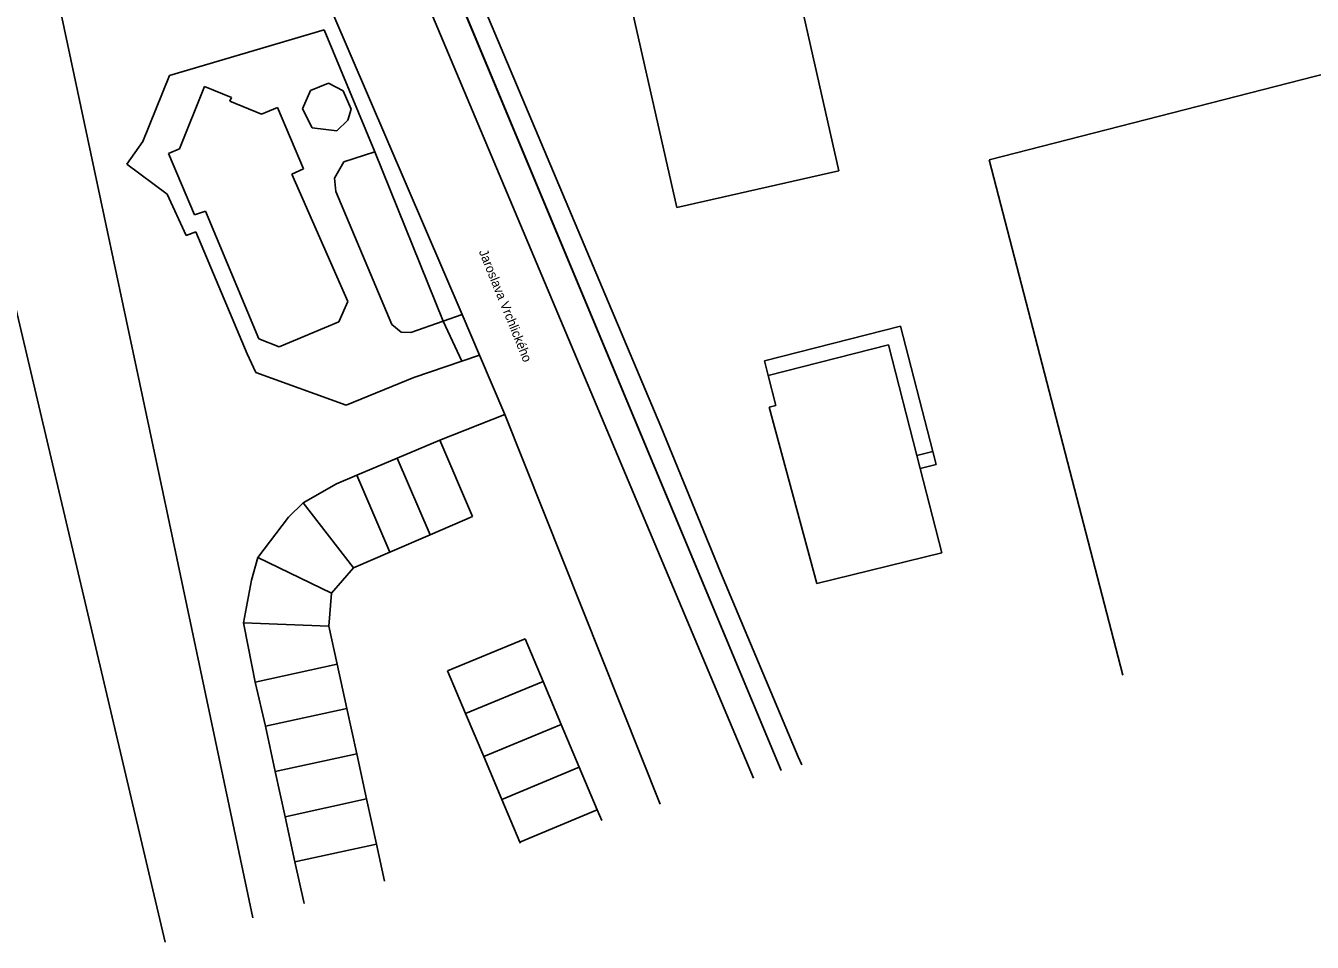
# Model space of a CAD drawing. Extents: x -452714 to -451134, y -1100194 to -1099694.
# Drawn here: x -451711.3 to -451613.9, y -1100007.9 to -1099938.4 of the extents above; entities that cross this region are included whole.
import ezdxf

# ---------------------------------------------------------------- set-up
doc = ezdxf.new("R2010")
doc.units = 0
doc.layers.add('Polohopis', color=7, linetype='Continuous')

msp = doc.modelspace()

# ---------------------------------------------------------------- linework, layer by layer
at = {"layer": 'Polohopis'}
for p, q in [((-451704.54, -1099873.82), (-451654.083, -1099994.837)), ((-451704.54, -1099873.82), (-451654.083, -1099994.837)), ((-451704.539, -1099873.82), (-451654.082, -1099994.836)), ((-451705.74, -1099877.629), (-451656.174, -1099995.42)), ((-451705.74, -1099877.63), (-451656.174, -1099995.42)), ((-451705.74, -1099877.63), (-451656.174, -1099995.42)), ((-451717.36, -1099896.27), (-451700.86, -1099973.87)), ((-451717.36, -1099896.27), (-451700.86, -1099973.87)), ((-451663.18, -1099968.8), (-451692.37, -1099899.639)), ((-451663.18, -1099968.8), (-451692.37, -1099899.64)), ((-451663.18, -1099968.8), (-451692.37, -1099899.64)), ((-451649.71, -1099949.42), (-451658.82, -1099909.22)), ((-451649.71, -1099949.42), (-451658.82, -1099909.22)), ((-451649.71, -1099949.42), (-451658.82, -1099909.22)), ((-451670.83, -1099913.11), (-451661.98, -1099952.2)), ((-451670.83, -1099913.11), (-451661.98, -1099952.2)), ((-451670.83, -1099913.11), (-451661.98, -1099952.2)), ((-451688.08, -1099937.34), (-451678.23, -1099960.31)), ((-451688.08, -1099937.34), (-451678.23, -1099960.31)), ((-451688.08, -1099937.34), (-451678.23, -1099960.31)), ((-451700.38, -1099942.2), (-451688.66, -1099938.74)), ((-451700.38, -1099942.2), (-451688.66, -1099938.74)), ((-451700.38, -1099942.2), (-451688.659, -1099938.74)), ((-451688.66, -1099938.74), (-451684.84, -1099947.99)), ((-451688.66, -1099938.74), (-451684.84, -1099947.99)), ((-451688.659, -1099938.74), (-451684.84, -1099947.99)), ((-451605.09, -1099940.08), (-451638.32, -1099948.6)), ((-451605.09, -1099940.08), (-451638.32, -1099948.6)), ((-451605.09, -1099940.08), (-451638.32, -1099948.6)), ((-451702.39, -1099947.2), (-451700.38, -1099942.2)), ((-451702.39, -1099947.2), (-451700.38, -1099942.2)), ((-451699.62, -1099947.76), (-451697.74, -1099943.04)), ((-451699.62, -1099947.76), (-451697.74, -1099943.04)), ((-451697.74, -1099943.04), (-451695.69, -1099943.88)), ((-451697.74, -1099943.04), (-451695.69, -1099943.88)), ((-451690.31, -1099944.73), (-451689.7, -1099943.35)), ((-451690.31, -1099944.73), (-451689.7, -1099943.35)), ((-451689.7, -1099943.35), (-451688.34, -1099942.8)), ((-451689.7, -1099943.35), (-451688.34, -1099942.8)), ((-451688.34, -1099942.8), (-451687.24, -1099943.36)), ((-451688.34, -1099942.8), (-451687.24, -1099943.36)), ((-451688.34, -1099942.8), (-451687.24, -1099943.36)), ((-451687.24, -1099943.36), (-451686.62, -1099944.75)), ((-451687.24, -1099943.36), (-451686.62, -1099944.75)), ((-451687.24, -1099943.36), (-451686.62, -1099944.75)), ((-451700.699, -1100007.851), (-451715.65, -1099944.45)), ((-451700.699, -1100007.851), (-451715.65, -1099944.45)), ((-451695.69, -1099943.88), (-451695.81, -1099944.16)), ((-451695.69, -1099943.88), (-451695.81, -1099944.16)), ((-451695.81, -1099944.16), (-451693.41, -1099945.15)), ((-451695.81, -1099944.16), (-451693.41, -1099945.15)), ((-451693.41, -1099945.15), (-451692.21, -1099944.64)), ((-451693.41, -1099945.15), (-451692.21, -1099944.64)), ((-451692.21, -1099944.64), (-451690.24, -1099949.28)), ((-451692.21, -1099944.64), (-451690.24, -1099949.28)), ((-451689.58, -1099946.18), (-451690.31, -1099944.73)), ((-451689.58, -1099946.18), (-451690.31, -1099944.73)), ((-451686.89, -1099945.58), (-451687.7, -1099946.39)), ((-451686.89, -1099945.58), (-451687.7, -1099946.39)), ((-451686.89, -1099945.58), (-451687.7, -1099946.389)), ((-451686.62, -1099944.75), (-451686.89, -1099945.58)), ((-451686.62, -1099944.75), (-451686.89, -1099945.58)), ((-451686.62, -1099944.75), (-451686.89, -1099945.58)), ((-451687.7, -1099946.39), (-451689.58, -1099946.18)), ((-451687.7, -1099946.39), (-451689.58, -1099946.18)), ((-451703.6, -1099948.92), (-451702.39, -1099947.2)), ((-451703.6, -1099948.92), (-451702.39, -1099947.2)), ((-451700.45, -1099948.11), (-451699.62, -1099947.76)), ((-451700.45, -1099948.11), (-451699.62, -1099947.76)), ((-451698.48, -1099952.77), (-451700.45, -1099948.11)), ((-451698.48, -1099952.77), (-451700.45, -1099948.11)), ((-451684.84, -1099947.99), (-451687.19, -1099948.74)), ((-451684.84, -1099947.99), (-451687.19, -1099948.74)), ((-451684.84, -1099947.99), (-451687.19, -1099948.74)), ((-451684.84, -1099947.99), (-451679.65, -1099960.81)), ((-451684.84, -1099947.99), (-451679.65, -1099960.81)), ((-451684.84, -1099947.99), (-451679.65, -1099960.81)), ((-451700.55, -1099951.19), (-451703.6, -1099948.92)), ((-451700.55, -1099951.19), (-451703.6, -1099948.92)), ((-451690.24, -1099949.28), (-451691.13, -1099949.67)), ((-451690.24, -1099949.28), (-451691.13, -1099949.67)), ((-451687.19, -1099948.74), (-451687.89, -1099949.98)), ((-451687.19, -1099948.74), (-451687.89, -1099949.98)), ((-451661.98, -1099952.2), (-451649.71, -1099949.42)), ((-451661.98, -1099952.2), (-451649.71, -1099949.42)), ((-451661.98, -1099952.2), (-451649.71, -1099949.42)), ((-451638.32, -1099948.6), (-451628.199, -1099987.61)), ((-451638.32, -1099948.6), (-451628.199, -1099987.61)), ((-451638.32, -1099948.6), (-451628.199, -1099987.61)), ((-451691.13, -1099949.67), (-451686.89, -1099959.32)), ((-451691.13, -1099949.67), (-451686.89, -1099959.32)), ((-451687.89, -1099949.98), (-451687.8, -1099950.99)), ((-451687.89, -1099949.98), (-451687.8, -1099950.99)), ((-451699.11, -1099954.33), (-451700.55, -1099951.19)), ((-451699.11, -1099954.33), (-451700.55, -1099951.19)), ((-451687.8, -1099950.99), (-451683.55, -1099961.06)), ((-451687.8, -1099950.99), (-451683.55, -1099961.06)), ((-451687.8, -1099950.99), (-451683.55, -1099961.06)), ((-451697.66, -1099952.48), (-451698.48, -1099952.77)), ((-451697.66, -1099952.48), (-451698.48, -1099952.77)), ((-451693.62, -1099962.16), (-451697.66, -1099952.48)), ((-451693.62, -1099962.16), (-451697.66, -1099952.48)), ((-451698.39, -1099954.05), (-451699.11, -1099954.33)), ((-451698.39, -1099954.05), (-451699.11, -1099954.33)), ((-451694.5, -1099963.29), (-451698.39, -1099954.05)), ((-451694.5, -1099963.29), (-451698.39, -1099954.05)), ((-451686.89, -1099959.32), (-451687.57, -1099960.86)), ((-451686.89, -1099959.32), (-451687.57, -1099960.86)), ((-451687.57, -1099960.86), (-451692.07, -1099962.77)), ((-451687.57, -1099960.86), (-451692.07, -1099962.77)), ((-451683.55, -1099961.06), (-451682.84, -1099961.65)), ((-451683.55, -1099961.06), (-451682.84, -1099961.65)), ((-451683.55, -1099961.06), (-451682.84, -1099961.65)), ((-451682.12, -1099961.67), (-451679.65, -1099960.81)), ((-451682.12, -1099961.67), (-451679.65, -1099960.81)), ((-451682.12, -1099961.67), (-451679.65, -1099960.81)), ((-451679.65, -1099960.81), (-451678.23, -1099960.31)), ((-451679.65, -1099960.81), (-451678.23, -1099960.31)), ((-451679.65, -1099960.81), (-451678.23, -1099960.31)), ((-451679.65, -1099960.81), (-451678.26, -1099963.85)), ((-451679.65, -1099960.81), (-451678.26, -1099963.85)), ((-451679.65, -1099960.81), (-451678.26, -1099963.85)), ((-451678.23, -1099960.31), (-451676.91, -1099963.39)), ((-451678.23, -1099960.31), (-451676.91, -1099963.39)), ((-451678.23, -1099960.31), (-451676.909, -1099963.389)), ((-451655.33, -1099963.83), (-451645.03, -1099961.2)), ((-451655.33, -1099963.83), (-451645.03, -1099961.2)), ((-451655.33, -1099963.83), (-451645.03, -1099961.2)), ((-451645.03, -1099961.2), (-451642.6, -1099970.68)), ((-451645.03, -1099961.2), (-451642.6, -1099970.68)), ((-451645.03, -1099961.2), (-451642.599, -1099970.68)), ((-451692.07, -1099962.77), (-451693.62, -1099962.16)), ((-451692.07, -1099962.77), (-451693.62, -1099962.16)), ((-451682.84, -1099961.65), (-451682.12, -1099961.67)), ((-451682.84, -1099961.65), (-451682.12, -1099961.67)), ((-451682.84, -1099961.65), (-451682.12, -1099961.67)), ((-451655.05, -1099964.94), (-451645.94, -1099962.6)), ((-451655.05, -1099964.94), (-451645.94, -1099962.6)), ((-451655.05, -1099964.94), (-451645.94, -1099962.6)), ((-451645.94, -1099962.6), (-451643.8, -1099970.99)), ((-451645.94, -1099962.6), (-451643.8, -1099970.99)), ((-451645.94, -1099962.6), (-451643.8, -1099970.99)), ((-451693.84, -1099964.71), (-451694.5, -1099963.29)), ((-451693.84, -1099964.71), (-451694.5, -1099963.29)), ((-451678.26, -1099963.85), (-451681.89, -1099965.09)), ((-451678.26, -1099963.85), (-451681.89, -1099965.09)), ((-451678.26, -1099963.85), (-451681.89, -1099965.09)), ((-451678.26, -1099963.85), (-451676.909, -1099963.389)), ((-451678.26, -1099963.85), (-451676.91, -1099963.39)), ((-451678.26, -1099963.85), (-451676.91, -1099963.39)), ((-451676.91, -1099963.39), (-451674.99, -1099967.87)), ((-451676.91, -1099963.39), (-451674.99, -1099967.87)), ((-451676.909, -1099963.389), (-451674.99, -1099967.87)), ((-451655.05, -1099964.94), (-451655.33, -1099963.83)), ((-451655.05, -1099964.94), (-451655.33, -1099963.83)), ((-451655.05, -1099964.94), (-451655.33, -1099963.83)), ((-451687.01, -1099967.17), (-451693.84, -1099964.71)), ((-451687.01, -1099967.17), (-451693.84, -1099964.71)), ((-451681.89, -1099965.09), (-451687.01, -1099967.17)), ((-451681.89, -1099965.09), (-451687.01, -1099967.17)), ((-451681.89, -1099965.09), (-451687.01, -1099967.17)), ((-451654.47, -1099967.19), (-451655.05, -1099964.94)), ((-451654.47, -1099967.19), (-451655.05, -1099964.94)), ((-451654.469, -1099967.19), (-451655.05, -1099964.94)), ((-451679.92, -1099969.82), (-451674.99, -1099967.87)), ((-451679.92, -1099969.82), (-451674.99, -1099967.87)), ((-451679.92, -1099969.82), (-451674.99, -1099967.87)), ((-451674.99, -1099967.87), (-451663.245, -1099997.394)), ((-451674.99, -1099967.87), (-451663.245, -1099997.394)), ((-451674.99, -1099967.87), (-451663.245, -1099997.394)), ((-451654.98, -1099967.32), (-451654.47, -1099967.19)), ((-451654.98, -1099967.32), (-451654.47, -1099967.19)), ((-451654.98, -1099967.32), (-451654.469, -1099967.19)), ((-451651.37, -1099980.67), (-451654.98, -1099967.32)), ((-451651.37, -1099980.67), (-451654.98, -1099967.32)), ((-451651.37, -1099980.67), (-451654.98, -1099967.32)), ((-451658.67, -1099979.83), (-451663.18, -1099968.8)), ((-451658.67, -1099979.83), (-451663.18, -1099968.8)), ((-451658.67, -1099979.83), (-451663.18, -1099968.8)), ((-451679.92, -1099969.82), (-451683.14, -1099971.18)), ((-451679.92, -1099969.82), (-451683.14, -1099971.18)), ((-451679.92, -1099969.82), (-451683.14, -1099971.18)), ((-451677.43, -1099975.61), (-451679.92, -1099969.82)), ((-451677.43, -1099975.61), (-451679.92, -1099969.82)), ((-451677.43, -1099975.61), (-451679.92, -1099969.82)), ((-451643.8, -1099970.99), (-451642.6, -1099970.68)), ((-451643.8, -1099970.99), (-451642.6, -1099970.68)), ((-451643.8, -1099970.99), (-451642.599, -1099970.68)), ((-451642.6, -1099970.68), (-451642.35, -1099971.66)), ((-451642.6, -1099970.68), (-451642.35, -1099971.66)), ((-451642.599, -1099970.68), (-451642.349, -1099971.66)), ((-451683.14, -1099971.18), (-451686.2, -1099972.48)), ((-451683.14, -1099971.18), (-451686.2, -1099972.48)), ((-451683.14, -1099971.18), (-451680.65, -1099976.99)), ((-451683.14, -1099971.18), (-451680.65, -1099976.99)), ((-451683.14, -1099971.18), (-451680.65, -1099976.99)), ((-451643.8, -1099970.99), (-451643.55, -1099971.96)), ((-451643.8, -1099970.99), (-451643.55, -1099971.96)), ((-451643.8, -1099970.99), (-451643.55, -1099971.96)), ((-451642.35, -1099971.66), (-451643.55, -1099971.96)), ((-451642.35, -1099971.66), (-451643.55, -1099971.96)), ((-451642.349, -1099971.66), (-451643.55, -1099971.96)), ((-451686.2, -1099972.48), (-451687.74, -1099973.13)), ((-451686.2, -1099972.48), (-451687.74, -1099973.13)), ((-451686.2, -1099972.48), (-451683.7, -1099978.3)), ((-451686.2, -1099972.48), (-451683.7, -1099978.3)), ((-451643.55, -1099971.96), (-451641.91, -1099978.37)), ((-451643.55, -1099971.96), (-451641.91, -1099978.37)), ((-451643.55, -1099971.96), (-451641.909, -1099978.37)), ((-451700.86, -1099973.87), (-451694.076, -1100006.002)), ((-451700.86, -1099973.87), (-451694.076, -1100006.002)), ((-451687.74, -1099973.13), (-451690.27, -1099974.58)), ((-451687.74, -1099973.13), (-451690.27, -1099974.58)), ((-451690.27, -1099974.58), (-451691.36, -1099975.65)), ((-451690.27, -1099974.58), (-451691.36, -1099975.65)), ((-451690.27, -1099974.58), (-451686.44, -1099979.5)), ((-451690.27, -1099974.58), (-451686.44, -1099979.5)), ((-451691.36, -1099975.65), (-451693.69, -1099978.7)), ((-451691.36, -1099975.65), (-451693.69, -1099978.7)), ((-451680.65, -1099976.99), (-451677.43, -1099975.61)), ((-451680.65, -1099976.99), (-451677.43, -1099975.61)), ((-451680.65, -1099976.99), (-451677.43, -1099975.61)), ((-451683.7, -1099978.3), (-451680.65, -1099976.99)), ((-451683.7, -1099978.3), (-451680.65, -1099976.99)), ((-451683.7, -1099978.3), (-451680.65, -1099976.99)), ((-451693.69, -1099978.7), (-451694.17, -1099980.44)), ((-451693.69, -1099978.7), (-451694.17, -1099980.44)), ((-451693.69, -1099978.7), (-451688.12, -1099981.4)), ((-451693.69, -1099978.7), (-451688.12, -1099981.4)), ((-451686.44, -1099979.5), (-451683.7, -1099978.3)), ((-451686.44, -1099979.5), (-451683.7, -1099978.3)), ((-451641.91, -1099978.37), (-451651.37, -1099980.67)), ((-451641.91, -1099978.37), (-451651.37, -1099980.67)), ((-451641.909, -1099978.37), (-451651.37, -1099980.67)), ((-451688.12, -1099981.4), (-451686.44, -1099979.5)), ((-451688.12, -1099981.4), (-451686.44, -1099979.5)), ((-451694.17, -1099980.44), (-451694.77, -1099983.65)), ((-451694.17, -1099980.44), (-451694.77, -1099983.65)), ((-451652.78, -1099993.8), (-451658.67, -1099979.83)), ((-451652.78, -1099993.8), (-451658.67, -1099979.83)), ((-451652.78, -1099993.8), (-451658.67, -1099979.83)), ((-451688.32, -1099983.9), (-451688.12, -1099981.4)), ((-451688.32, -1099983.9), (-451688.12, -1099981.4)), ((-451694.77, -1099983.65), (-451694.42, -1099985.46)), ((-451694.77, -1099983.65), (-451688.32, -1099983.9)), ((-451694.77, -1099983.65), (-451694.42, -1099985.46)), ((-451694.77, -1099983.65), (-451688.32, -1099983.9)), ((-451687.68, -1099986.8), (-451688.32, -1099983.9)), ((-451687.68, -1099986.8), (-451688.32, -1099983.9)), ((-451694.42, -1099985.46), (-451693.89, -1099988.14)), ((-451694.42, -1099985.46), (-451693.89, -1099988.14)), ((-451679.33, -1099987.29), (-451673.46, -1099984.86)), ((-451679.33, -1099987.29), (-451673.46, -1099984.86)), ((-451679.33, -1099987.29), (-451673.46, -1099984.86)), ((-451673.46, -1099984.86), (-451672.09, -1099988.11)), ((-451673.46, -1099984.86), (-451672.09, -1099988.11)), ((-451673.46, -1099984.86), (-451672.09, -1099988.11)), ((-451693.89, -1099988.14), (-451687.68, -1099986.8)), ((-451693.89, -1099988.14), (-451687.68, -1099986.8)), ((-451686.96, -1099990.15), (-451687.68, -1099986.8)), ((-451686.96, -1099990.15), (-451687.68, -1099986.8)), ((-451677.96, -1099990.52), (-451679.33, -1099987.29)), ((-451677.96, -1099990.52), (-451679.33, -1099987.29)), ((-451677.96, -1099990.52), (-451679.33, -1099987.29)), ((-451693.89, -1099988.14), (-451693.11, -1099991.49)), ((-451693.89, -1099988.14), (-451693.11, -1099991.49)), ((-451677.96, -1099990.52), (-451672.09, -1099988.11)), ((-451677.96, -1099990.52), (-451672.09, -1099988.11)), ((-451677.96, -1099990.52), (-451672.09, -1099988.11)), ((-451672.09, -1099988.11), (-451670.73, -1099991.35)), ((-451672.09, -1099988.11), (-451670.73, -1099991.35)), ((-451672.09, -1099988.11), (-451670.73, -1099991.35)), ((-451693.11, -1099991.49), (-451686.96, -1099990.15)), ((-451693.11, -1099991.49), (-451686.96, -1099990.15)), ((-451686.21, -1099993.58), (-451686.96, -1099990.15)), ((-451686.21, -1099993.58), (-451686.96, -1099990.15)), ((-451676.59, -1099993.77), (-451677.96, -1099990.52)), ((-451676.59, -1099993.77), (-451677.96, -1099990.52)), ((-451676.59, -1099993.77), (-451677.96, -1099990.52)), ((-451676.59, -1099993.77), (-451670.73, -1099991.35)), ((-451676.59, -1099993.77), (-451670.73, -1099991.35)), ((-451676.59, -1099993.77), (-451670.73, -1099991.35)), ((-451670.73, -1099991.35), (-451669.36, -1099994.59)), ((-451670.73, -1099991.35), (-451669.36, -1099994.59)), ((-451670.73, -1099991.35), (-451669.36, -1099994.59)), ((-451693.11, -1099991.49), (-451692.37, -1099994.92)), ((-451693.11, -1099991.49), (-451692.37, -1099994.92)), ((-451692.37, -1099994.92), (-451686.21, -1099993.58)), ((-451692.37, -1099994.92), (-451686.21, -1099993.58)), ((-451685.47, -1099997), (-451686.21, -1099993.58)), ((-451685.47, -1099997), (-451686.21, -1099993.58)), ((-451675.21, -1099997.03), (-451676.59, -1099993.77)), ((-451675.21, -1099997.03), (-451676.59, -1099993.77)), ((-451675.21, -1099997.03), (-451676.59, -1099993.77)), ((-451652.521, -1099994.401), (-451652.78, -1099993.8)), ((-451652.521, -1099994.401), (-451652.78, -1099993.8)), ((-451652.521, -1099994.401), (-451652.78, -1099993.8)), ((-451692.37, -1099994.92), (-451691.63, -1099998.34)), ((-451692.37, -1099994.92), (-451691.63, -1099998.34)), ((-451675.21, -1099997.03), (-451669.36, -1099994.59)), ((-451675.21, -1099997.03), (-451669.36, -1099994.59)), ((-451675.21, -1099997.03), (-451669.36, -1099994.59)), ((-451669.36, -1099994.59), (-451668, -1099997.82)), ((-451669.36, -1099994.59), (-451668, -1099997.82)), ((-451669.36, -1099994.59), (-451668, -1099997.82)), ((-451691.63, -1099998.34), (-451685.47, -1099997)), ((-451691.63, -1099998.34), (-451685.47, -1099997)), ((-451684.72, -1100000.42), (-451685.47, -1099997)), ((-451684.72, -1100000.42), (-451685.47, -1099997)), ((-451673.85, -1100000.26), (-451675.21, -1099997.03)), ((-451673.85, -1100000.26), (-451675.21, -1099997.03)), ((-451673.849, -1100000.26), (-451675.21, -1099997.03)), ((-451673.85, -1100000.26), (-451668, -1099997.82)), ((-451673.85, -1100000.26), (-451668, -1099997.82)), ((-451673.849, -1100000.26), (-451668, -1099997.82)), ((-451668, -1099997.82), (-451667.661, -1099998.627)), ((-451668, -1099997.82), (-451667.661, -1099998.627)), ((-451668, -1099997.82), (-451667.661, -1099998.627)), ((-451691.63, -1099998.34), (-451690.88, -1100001.76)), ((-451691.63, -1099998.34), (-451690.88, -1100001.76)), ((-451690.88, -1100001.76), (-451684.72, -1100000.42)), ((-451690.88, -1100001.76), (-451684.72, -1100000.42)), ((-451684.114, -1100003.221), (-451684.72, -1100000.42)), ((-451684.114, -1100003.221), (-451684.72, -1100000.42)), ((-451673.814, -1100000.345), (-451673.85, -1100000.26)), ((-451673.814, -1100000.345), (-451673.85, -1100000.26)), ((-451673.813, -1100000.345), (-451673.849, -1100000.26)), ((-451690.88, -1100001.76), (-451690.197, -1100004.919)), ((-451690.88, -1100001.76), (-451690.197, -1100004.919))]:
    msp.add_line(p, q, dxfattribs=at)

# ---------------------------------------------------------------- texts
msp.add_text('Jaroslava Vrchlického', height=0.7, rotation=292, dxfattribs=at).set_placement((-451676.974, -1099955.543))
msp.add_text('Jaroslava Vrchlického', height=0.7, rotation=292, dxfattribs=at).set_placement((-451676.974, -1099955.543))

doc.saveas('drawing.dxf')
